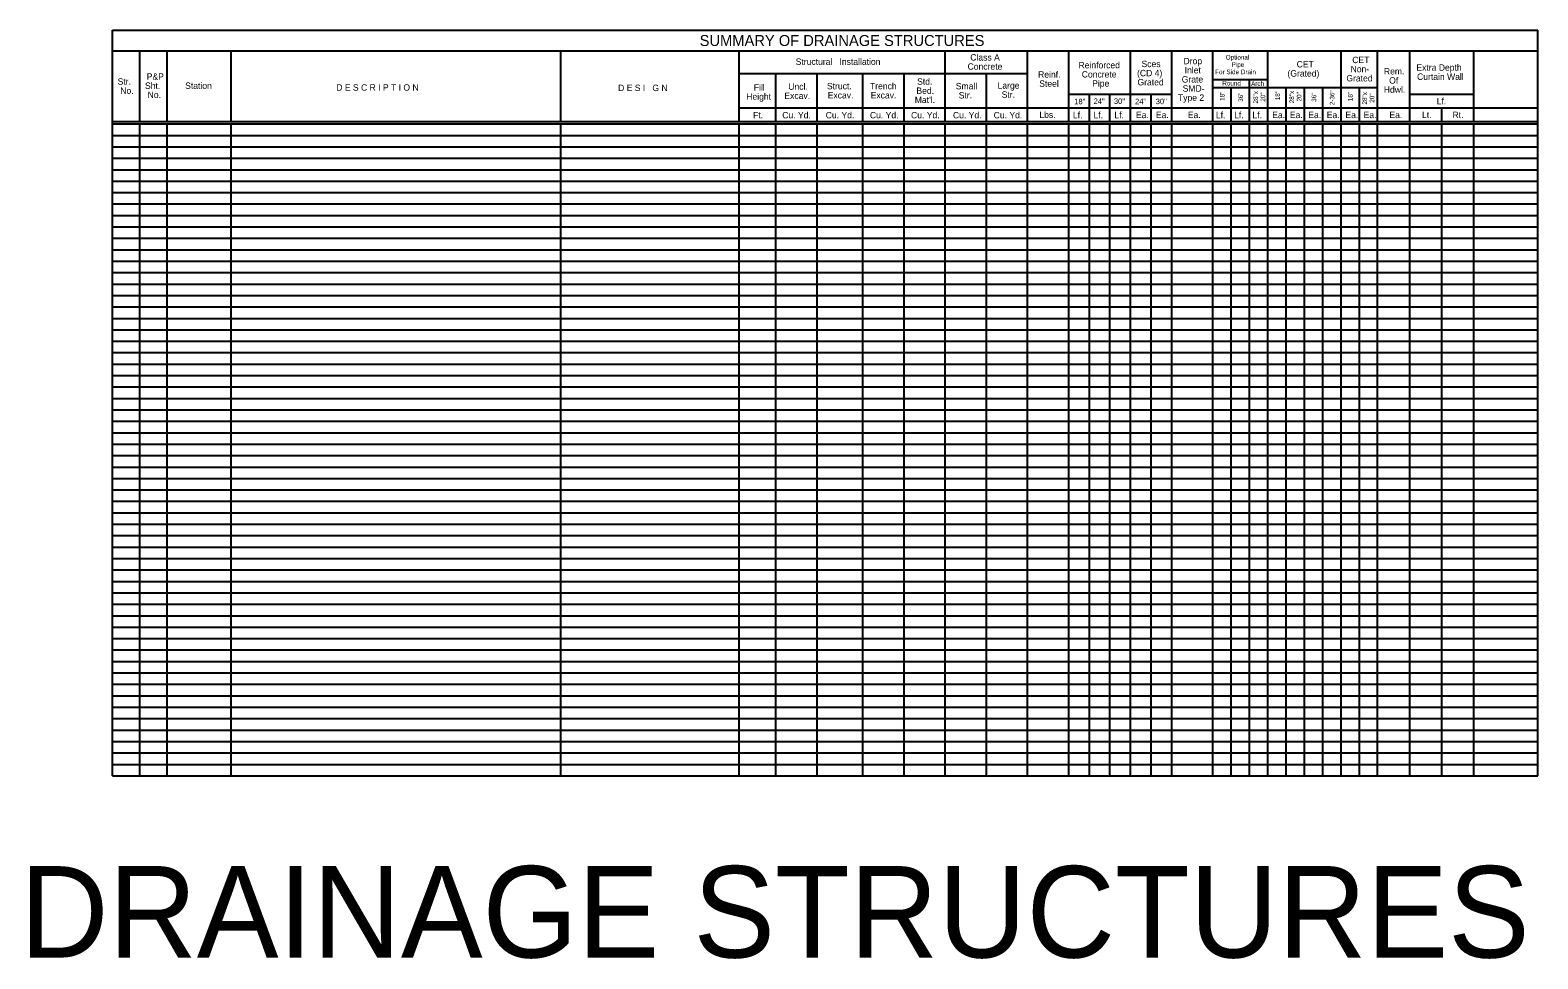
# Model space of a CAD drawing. Extents: x 1790274 to 1791453, y 1790011 to 1790884.
# Drawn here: x 1790274.2 to 1790603.7, y 1790678.3 to 1790881.4 of the extents above; entities that cross this region are included whole.
import ezdxf

# ---------------------------------------------------------------- set-up
doc = ezdxf.new("R2010")
doc.units = 0
doc.layers.add('Level 1', color=7, linetype='Continuous')
doc.layers.add('Level 2', color=7, linetype='Continuous')

msp = doc.modelspace()

# ---------------------------------------------------------------- linework, layer by layer
at = {"layer": 'Level 1'}
for p, q in [((1790292.15, 1790881.37), (1790603.65, 1790881.37)), ((1790292.15, 1790718.37), (1790292.15, 1790881.37)), ((1790603.65, 1790718.37), (1790603.65, 1790881.37)), ((1790292.15, 1790876.87), (1790603.65, 1790876.87)), ((1790298.15, 1790861.37), (1790298.15, 1790876.87)), ((1790304.15, 1790861.37), (1790304.15, 1790876.87)), ((1790318.15, 1790861.37), (1790318.15, 1790876.87)), ((1790390.15, 1790861.37), (1790390.15, 1790876.87)), ((1790429.15, 1790861.37), (1790429.15, 1790876.87)), ((1790474.15, 1790861.37), (1790474.15, 1790876.87)), ((1790492.15, 1790861.37), (1790492.15, 1790876.87)), ((1790501.15, 1790861.37), (1790501.15, 1790876.87)), ((1790514.65, 1790861.37), (1790514.65, 1790876.87)), ((1790523.65, 1790861.37), (1790523.65, 1790876.87)), ((1790532.65, 1790861.37), (1790532.65, 1790876.87)), ((1790544.65, 1790861.37), (1790544.65, 1790876.87)), ((1790560.65, 1790861.37), (1790560.65, 1790876.87)), ((1790568.65, 1790861.37), (1790568.65, 1790876.87)), ((1790575.65, 1790861.37), (1790575.65, 1790876.87)), ((1790589.65, 1790861.37), (1790589.65, 1790876.87)), ((1790429.15, 1790871.87), (1790492.15, 1790871.87)), ((1790437.15, 1790861.37), (1790437.15, 1790871.87)), ((1790446.15, 1790861.37), (1790446.15, 1790871.87)), ((1790456.15, 1790861.37), (1790456.15, 1790871.87)), ((1790465.15, 1790861.37), (1790465.15, 1790871.87)), ((1790483.15, 1790861.37), (1790483.15, 1790871.87)), ((1790532.65, 1790870.57), (1790544.65, 1790870.57)), ((1790532.65, 1790868.87), (1790568.65, 1790868.87)), ((1790536.65, 1790861.37), (1790536.65, 1790868.87)), ((1790540.65, 1790861.37), (1790540.65, 1790870.57)), ((1790548.65, 1790861.37), (1790548.65, 1790868.87)), ((1790552.65, 1790861.37), (1790552.65, 1790868.87)), ((1790556.65, 1790861.37), (1790556.65, 1790868.87)), ((1790564.65, 1790861.37), (1790564.65, 1790868.87)), ((1790501.15, 1790867.37), (1790523.65, 1790867.37)), ((1790505.65, 1790861.37), (1790505.65, 1790867.37)), ((1790510.15, 1790861.37), (1790510.15, 1790867.37)), ((1790519.15, 1790861.37), (1790519.15, 1790867.37)), ((1790575.65, 1790867.37), (1790589.65, 1790867.37)), ((1790429.15, 1790864.37), (1790603.65, 1790864.37)), ((1790582.65, 1790861.37), (1790582.65, 1790864.37)), ((1790292.15, 1790861.37), (1790603.65, 1790861.37)), ((1790292.15, 1790860.87), (1790603.65, 1790860.87)), ((1790292.15, 1790858.37), (1790603.65, 1790858.37)), ((1790298.15, 1790718.37), (1790298.15, 1790860.87)), ((1790304.15, 1790718.37), (1790304.15, 1790860.87)), ((1790318.15, 1790718.37), (1790318.15, 1790860.87)), ((1790390.15, 1790718.37), (1790390.15, 1790860.87)), ((1790429.15, 1790718.37), (1790429.15, 1790860.87)), ((1790437.15, 1790718.37), (1790437.15, 1790860.87)), ((1790446.15, 1790718.37), (1790446.15, 1790860.87)), ((1790456.15, 1790718.37), (1790456.15, 1790860.87)), ((1790465.15, 1790718.37), (1790465.15, 1790860.87)), ((1790474.15, 1790718.37), (1790474.15, 1790860.87)), ((1790483.15, 1790718.37), (1790483.15, 1790860.87)), ((1790492.15, 1790718.37), (1790492.15, 1790860.87)), ((1790501.15, 1790718.37), (1790501.15, 1790860.87)), ((1790505.65, 1790718.37), (1790505.65, 1790860.87)), ((1790510.15, 1790718.37), (1790510.15, 1790860.87)), ((1790514.65, 1790718.37), (1790514.65, 1790860.87)), ((1790519.15, 1790718.37), (1790519.15, 1790860.87)), ((1790523.65, 1790718.37), (1790523.65, 1790860.87)), ((1790532.65, 1790718.37), (1790532.65, 1790860.87)), ((1790536.65, 1790718.37), (1790536.65, 1790860.87)), ((1790540.65, 1790718.37), (1790540.65, 1790860.87)), ((1790544.65, 1790718.37), (1790544.65, 1790860.87)), ((1790548.65, 1790718.37), (1790548.65, 1790860.87)), ((1790552.65, 1790718.37), (1790552.65, 1790860.87)), ((1790556.65, 1790718.37), (1790556.65, 1790860.87)), ((1790560.65, 1790718.37), (1790560.65, 1790860.87)), ((1790564.65, 1790718.37), (1790564.65, 1790860.87)), ((1790568.65, 1790718.37), (1790568.65, 1790860.87)), ((1790575.65, 1790718.37), (1790575.65, 1790860.87)), ((1790582.65, 1790718.37), (1790582.65, 1790860.87)), ((1790589.65, 1790718.37), (1790589.65, 1790860.87)), ((1790292.15, 1790855.87), (1790603.65, 1790855.87)), ((1790292.15, 1790853.37), (1790603.65, 1790853.37)), ((1790292.15, 1790850.87), (1790603.65, 1790850.87)), ((1790292.15, 1790848.37), (1790603.65, 1790848.37)), ((1790292.15, 1790845.87), (1790603.65, 1790845.87)), ((1790292.15, 1790843.37), (1790603.65, 1790843.37)), ((1790292.15, 1790840.87), (1790603.65, 1790840.87)), ((1790292.15, 1790838.37), (1790603.65, 1790838.37)), ((1790292.15, 1790835.87), (1790603.65, 1790835.87)), ((1790292.15, 1790833.37), (1790603.65, 1790833.37)), ((1790292.15, 1790830.87), (1790603.65, 1790830.87)), ((1790292.15, 1790828.37), (1790603.65, 1790828.37)), ((1790292.15, 1790825.87), (1790603.65, 1790825.87)), ((1790292.15, 1790823.37), (1790603.65, 1790823.37)), ((1790292.15, 1790820.87), (1790603.65, 1790820.87)), ((1790292.15, 1790818.37), (1790603.65, 1790818.37)), ((1790292.15, 1790815.87), (1790603.65, 1790815.87)), ((1790292.15, 1790813.37), (1790603.65, 1790813.37)), ((1790292.15, 1790810.87), (1790603.65, 1790810.87)), ((1790292.15, 1790808.37), (1790603.65, 1790808.37)), ((1790292.15, 1790805.87), (1790603.65, 1790805.87)), ((1790292.15, 1790803.37), (1790603.65, 1790803.37)), ((1790292.15, 1790800.87), (1790603.65, 1790800.87)), ((1790292.15, 1790798.37), (1790603.65, 1790798.37)), ((1790292.15, 1790795.87), (1790603.65, 1790795.87)), ((1790292.15, 1790793.37), (1790603.65, 1790793.37)), ((1790292.15, 1790790.87), (1790603.65, 1790790.87)), ((1790292.15, 1790788.37), (1790603.65, 1790788.37)), ((1790292.15, 1790785.87), (1790603.65, 1790785.87)), ((1790292.15, 1790783.37), (1790603.65, 1790783.37)), ((1790292.15, 1790780.87), (1790603.65, 1790780.87)), ((1790292.15, 1790778.37), (1790603.65, 1790778.37)), ((1790292.15, 1790775.87), (1790603.65, 1790775.87)), ((1790292.15, 1790773.37), (1790603.65, 1790773.37)), ((1790292.15, 1790770.87), (1790603.65, 1790770.87)), ((1790292.15, 1790768.37), (1790603.65, 1790768.37)), ((1790292.15, 1790765.87), (1790603.65, 1790765.87)), ((1790292.15, 1790763.37), (1790603.65, 1790763.37)), ((1790292.15, 1790760.87), (1790603.65, 1790760.87)), ((1790292.15, 1790758.37), (1790603.65, 1790758.37)), ((1790292.15, 1790755.87), (1790603.65, 1790755.87)), ((1790292.15, 1790753.37), (1790603.65, 1790753.37)), ((1790292.15, 1790750.87), (1790603.65, 1790750.87)), ((1790292.15, 1790748.37), (1790603.65, 1790748.37)), ((1790292.15, 1790745.87), (1790603.65, 1790745.87)), ((1790292.15, 1790743.37), (1790603.65, 1790743.37)), ((1790292.15, 1790740.87), (1790603.65, 1790740.87)), ((1790292.15, 1790738.37), (1790603.65, 1790738.37)), ((1790292.15, 1790735.87), (1790603.65, 1790735.87)), ((1790292.15, 1790733.37), (1790603.65, 1790733.37)), ((1790292.15, 1790730.87), (1790603.65, 1790730.87)), ((1790292.15, 1790728.37), (1790603.65, 1790728.37)), ((1790292.15, 1790725.87), (1790603.65, 1790725.87)), ((1790292.15, 1790723.37), (1790603.65, 1790723.37)), ((1790292.15, 1790720.87), (1790603.65, 1790720.87)), ((1790292.15, 1790718.37), (1790603.65, 1790718.37))]:
    msp.add_line(p, q, dxfattribs=at)

# ---------------------------------------------------------------- texts
at = {"layer": 'Level 2'}
for s, height, p in [('SUMMARY OF DRAINAGE STRUCTURES', 2.4, (1790420.49, 1790877.91)), ('Structural   Installation', 1.4, (1790441.48, 1790873.78)), ('Class A', 1.4, (1790479.63, 1790874.72)), ('Drop', 1.4, (1790526.23, 1790873.92)), ('Optional', 1, (1790535.45, 1790874.94)), ('CET', 1.4, (1790563.1, 1790874.16)), ('P&P', 1.4, (1790299.67, 1790870.53)), ('Concrete', 1.4, (1790479.04, 1790872.72)), ('Reinf.', 1.4, (1790494.45, 1790870.98)), ('Reinforced', 1.4, (1790503.28, 1790873.02)), ('Concrete', 1.4, (1790503.99, 1790871.02)), ('(CD 4)', 1.4, (1790516.07, 1790871.29)), ('Sces', 1.4, (1790517.05, 1790873.29)), ('Inlet', 1.4, (1790526.48, 1790871.92)), ('For Side Drain', 1, (1790533.15, 1790871.74)), ('Pipe', 1, (1790536.74, 1790873.34)), ('(Grated)', 1.4, (1790548.94, 1790871.22)), ('CET', 1.4, (1790550.95, 1790873.22)), ('Grated', 1.4, (1790561.82, 1790870.16)), ('Non-', 1.4, (1790562.74, 1790872.16)), ('Rem.', 1.4, (1790570.02, 1790871.68)), ('Extra Depth', 1.4, (1790577.12, 1790872.5)), ('Curtain Wall', 1.4, (1790577.26, 1790870.5)), ('Str.', 1.4, (1790293.31, 1790869.44)), ('No.', 1.4, (1790293.89, 1790867.44)), ('Sht.', 1.4, (1790299.29, 1790868.53)), ('Station', 1.4, (1790308.06, 1790868.54)), ('D E S C R I P T I O N', 1.4, (1790341.09, 1790868.14)), ('D E S I   G N', 1.4, (1790402.67, 1790868.05)), ('Fill', 1.4, (1790432.32, 1790868.15)), ('Uncl.', 1.4, (1790439.86, 1790868.34)), ('Struct.', 1.4, (1790448.31, 1790868.44)), ('Trench', 1.4, (1790457.71, 1790868.44)), ('Bed.', 1.4, (1790467.86, 1790867.44)), ('Std.', 1.4, (1790468.01, 1790869.44)), ('Small', 1.4, (1790476.46, 1790868.44)), ('Large', 1.4, (1790485.6, 1790868.58)), ('Steel', 1.4, (1790494.7, 1790868.98)), ('Pipe', 1.4, (1790506.26, 1790869.02)), ('Grated', 1.4, (1790516.17, 1790869.29)), ('Grate', 1.4, (1790525.83, 1790869.92)), ('SMD-', 1.4, (1790526.04, 1790867.92)), ('Round', 1, (1790534.7, 1790869.27)), ('Arch', 1, (1790540.99, 1790869.19)), ('Hdwl.', 1.4, (1790569.99, 1790867.68)), ('Of', 1.4, (1790571.16, 1790869.68)), ('No.', 1.4, (1790299.87, 1790866.53)), ('Height', 1.4, (1790430.68, 1790866.15)), ('Excav.', 1.4, (1790439.01, 1790866.34)), ('Excav.', 1.4, (1790448.48, 1790866.44)), ('Excav.', 1.4, (1790457.86, 1790866.44)), ("Mat'l.", 1.4, (1790467.5, 1790865.44)), ('Str.', 1.4, (1790477.1, 1790866.44)), ('Str.', 1.4, (1790486.49, 1790866.58)), ('18"', 1.2, (1790502.34, 1790865.18)), ('24"', 1.2, (1790506.58, 1790865.24)), ('30"', 1.2, (1790511.01, 1790865.24)), ('24"', 1.2, (1790515.63, 1790865.19)), ('30"', 1.2, (1790520.15, 1790865.19)), ('Type 2', 1.4, (1790525.01, 1790865.92)), ('Lf.', 1.4, (1790581.56, 1790865.16)), ('Ft.', 1.4, (1790432.16, 1790862.09)), ('Cu. Yd.', 1.4, (1790438.54, 1790862.09)), ('Cu. Yd.', 1.4, (1790448.04, 1790862.09)), ('Cu. Yd.', 1.4, (1790457.7, 1790862.09)), ('Cu. Yd.', 1.4, (1790466.69, 1790862.09)), ('Cu. Yd.', 1.4, (1790475.85, 1790862.09)), ('Cu. Yd.', 1.4, (1790484.74, 1790862.09)), ('Lbs.', 1.4, (1790494.73, 1790862.17)), ('Lf.', 1.4, (1790502.06, 1790862.12)), ('Lf.', 1.4, (1790506.56, 1790862.12)), ('Lf.', 1.4, (1790511.11, 1790862.12)), ('Ea.', 1.4, (1790515.84, 1790862.14)), ('Ea.', 1.4, (1790520.19, 1790862.14)), ('Ea.', 1.4, (1790527.16, 1790862.14)), ('Lf.', 1.4, (1790533.3, 1790862.12)), ('Lf.', 1.4, (1790537.29, 1790862.12)), ('Lf.', 1.4, (1790541.29, 1790862.12)), ('Ea.', 1.4, (1790545.6, 1790862.14)), ('Ea.', 1.4, (1790549.46, 1790862.14)), ('Ea.', 1.4, (1790553.49, 1790862.14)), ('Ea.', 1.4, (1790557.52, 1790862.14)), ('Ea.', 1.4, (1790561.6, 1790862.14)), ('Ea.', 1.4, (1790565.58, 1790862.14)), ('Ea.', 1.4, (1790571.21, 1790862.14)), ('Lt.', 1.4, (1790578.34, 1790862.14)), ('Rt.', 1.4, (1790585.01, 1790862.14)), ('DRAINAGE STRUCTURES', 20, (1790272, 1790678.63))]:
    msp.add_text(s, height=height, dxfattribs=at).set_placement(p)
for s, p in [('18"', (1790535.18, 1790865.91)), ('36"', (1790539.2, 1790865.7)), ('28"x', (1790542.48, 1790865.34)), ('20"', (1790544.08, 1790865.74)), ('18"', (1790547.28, 1790866.05)), ('28"x', (1790550.37, 1790865.39)), ('20"', (1790551.97, 1790865.79)), ('36"', (1790555.22, 1790865.71)), ('2-36"', (1790559.2, 1790864.97)), ('18"', (1790563.16, 1790865.85)), ('28"x', (1790566.31, 1790865.11)), ('20"', (1790567.91, 1790865.51))]:
    msp.add_text(s, height=1, rotation=90, dxfattribs=at).set_placement(p)

doc.saveas('drawing.dxf')
